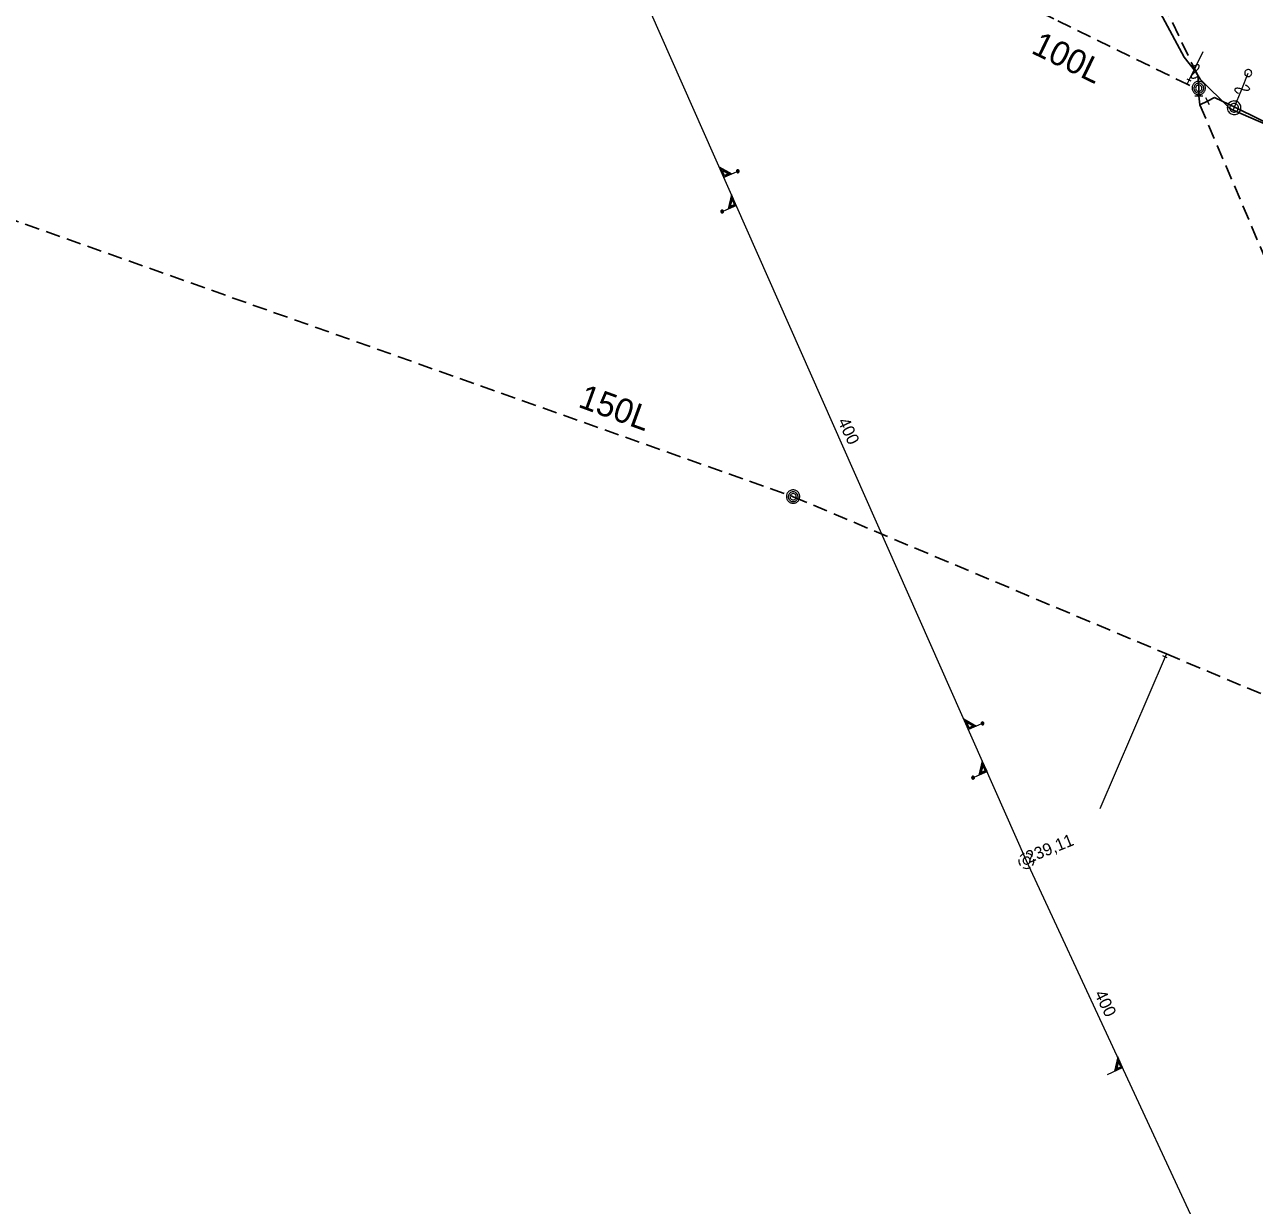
# Model space of a CAD drawing. Extents: x -735085 to -733500, y -1044153 to -1043402.
# Drawn here: x -734892.7 to -734812.1, y -1043597 to -1043519.6 of the extents above; entities that cross this region are included whole.
import ezdxf

# ---------------------------------------------------------------- set-up
doc = ezdxf.new("R2010")
doc.units = 0
doc.header["$LTSCALE"] = 0.32
doc.linetypes.add('MEDIUM_DASHED', pattern=[4.5, 3, -1.5])
doc.layers.add('15', color=7, linetype='Continuous')
doc.layers.add('16', color=7, linetype='Continuous')
for name, color, linetype, lineweight in [('18', 7, 'Continuous', 13), ('20', 7, 'Continuous', 13), ('8', 7, 'Continuous', 13)]:
    doc.layers.add(name, color=color, linetype=linetype, lineweight=lineweight)

msp = doc.modelspace()

# ---------------------------------------------------------------- linework, layer by layer
at = {"layer": '18'}
for points in [[(-734845.879, -1043529.18), (-734846.88, -1043529.624), (-734847.192, -1043528.92), (-734846.352, -1043529.389)], [(-734846.48, -1043529.391), (-734846.86, -1043529.56), (-734847.089, -1043529.043), (-734846.479, -1043529.391)], [(-734846.576, -1043529.383), (-734846.842, -1043529.501), (-734846.993, -1043529.161), (-734846.575, -1043529.383)], [(-734847.077, -1043531.897), (-734846.076, -1043531.453), (-734846.389, -1043530.748), (-734846.605, -1043531.687)], [(-734846.517, -1043531.593), (-734846.136, -1043531.424), (-734846.366, -1043530.907), (-734846.518, -1043531.593)], [(-734846.46, -1043531.516), (-734846.193, -1043531.398), (-734846.343, -1043531.058), (-734846.459, -1043531.517)], [(-734829.833, -1043565.381), (-734830.834, -1043565.825), (-734831.146, -1043565.121), (-734830.306, -1043565.59)], [(-734830.434, -1043565.592), (-734830.814, -1043565.761), (-734831.043, -1043565.244), (-734830.433, -1043565.592)], [(-734830.53, -1043565.584), (-734830.796, -1043565.702), (-734830.947, -1043565.362), (-734830.529, -1043565.584)], [(-734830.625, -1043569.012), (-734829.624, -1043568.568), (-734829.937, -1043567.863), (-734830.153, -1043568.802)], [(-734830.065, -1043568.708), (-734829.684, -1043568.539), (-734829.914, -1043568.022), (-734830.066, -1043568.708)], [(-734830.008, -1043568.631), (-734829.741, -1043568.513), (-734829.891, -1043568.173), (-734830.007, -1043568.632)], [(-734827.528, -1043574.349), (-734827.534, -1043574.426), (-734827.529, -1043574.503), (-734827.512, -1043574.578), (-734827.483, -1043574.649), (-734827.443, -1043574.715), (-734827.427, -1043574.737)], [(-734827.183, -1043573.957), (-734827.254, -1043573.985), (-734827.321, -1043574.024), (-734827.381, -1043574.072), (-734827.432, -1043574.129), (-734827.456, -1043574.163)], [(-734826.642, -1043574.14), (-734826.692, -1043574.082), (-734826.75, -1043574.032), (-734826.815, -1043573.991), (-734826.886, -1043573.962), (-734826.935, -1043573.948)], [(-734826.647, -1043574.726), (-734826.606, -1043574.661), (-734826.575, -1043574.591), (-734826.556, -1043574.516), (-734826.548, -1043574.44), (-734826.553, -1043574.363), (-734826.559, -1043574.328)], [(-734827.27, -1043574.866), (-734827.2, -1043574.897), (-734827.125, -1043574.916), (-734827.049, -1043574.923), (-734826.972, -1043574.918), (-734826.897, -1043574.901), (-734826.825, -1043574.873), (-734826.765, -1043574.838)], [(-734821.725, -1043588.443), (-734820.731, -1043587.982), (-734821.056, -1043587.282), (-734821.255, -1043588.225)], [(-734821.17, -1043588.129), (-734820.792, -1043587.954), (-734821.03, -1043587.442), (-734821.171, -1043588.13)], [(-734821.113, -1043588.051), (-734820.849, -1043587.929), (-734821.005, -1043587.592), (-734821.113, -1043588.052)]]:
    msp.add_lwpolyline(points, dxfattribs=at)
for points in [[(-734846.003, -1043529.132), (-734846.031, -1043529.151), (-734846.05, -1043529.178), (-734846.059, -1043529.21), (-734846.055, -1043529.244), (-734846.041, -1043529.274), (-734846.016, -1043529.297), (-734845.985, -1043529.31), (-734845.952, -1043529.312), (-734845.92, -1043529.301), (-734845.894, -1043529.281), (-734845.876, -1043529.252), (-734845.87, -1043529.219), (-734845.876, -1043529.186), (-734845.893, -1043529.156), (-734845.918, -1043529.135), (-734845.95, -1043529.125), (-734845.984, -1043529.126)], [(-734845.993, -1043529.157), (-734846.016, -1043529.174), (-734846.031, -1043529.198), (-734846.032, -1043529.226), (-734846.024, -1043529.253), (-734846.005, -1043529.274), (-734845.978, -1043529.284), (-734845.95, -1043529.284), (-734845.925, -1043529.271), (-734845.907, -1043529.25), (-734845.899, -1043529.223), (-734845.903, -1043529.195), (-734845.918, -1043529.171), (-734845.942, -1043529.155), (-734845.969, -1043529.151)], [(-734847.03, -1043531.772), (-734847.058, -1043531.791), (-734847.077, -1043531.818), (-734847.086, -1043531.85), (-734847.082, -1043531.884), (-734847.068, -1043531.913), (-734847.043, -1043531.937), (-734847.012, -1043531.95), (-734846.979, -1043531.952), (-734846.947, -1043531.942), (-734846.92, -1043531.92), (-734846.903, -1043531.892), (-734846.897, -1043531.86), (-734846.903, -1043531.826), (-734846.919, -1043531.797), (-734846.945, -1043531.776), (-734846.977, -1043531.765), (-734847.011, -1043531.766)], [(-734847.017, -1043531.796), (-734847.04, -1043531.813), (-734847.054, -1043531.838), (-734847.058, -1043531.865), (-734847.048, -1043531.892), (-734847.029, -1043531.913), (-734847.003, -1043531.924), (-734846.975, -1043531.924), (-734846.949, -1043531.911), (-734846.931, -1043531.889), (-734846.923, -1043531.862), (-734846.927, -1043531.834), (-734846.942, -1043531.811), (-734846.966, -1043531.795), (-734846.994, -1043531.79)], [(-734829.957, -1043565.333), (-734829.985, -1043565.352), (-734830.004, -1043565.379), (-734830.013, -1043565.411), (-734830.009, -1043565.445), (-734829.995, -1043565.475), (-734829.97, -1043565.498), (-734829.939, -1043565.511), (-734829.906, -1043565.513), (-734829.874, -1043565.502), (-734829.848, -1043565.482), (-734829.83, -1043565.453), (-734829.824, -1043565.42), (-734829.83, -1043565.387), (-734829.847, -1043565.357), (-734829.872, -1043565.336), (-734829.904, -1043565.326), (-734829.938, -1043565.327)], [(-734829.947, -1043565.358), (-734829.97, -1043565.375), (-734829.985, -1043565.399), (-734829.986, -1043565.427), (-734829.978, -1043565.454), (-734829.959, -1043565.475), (-734829.932, -1043565.485), (-734829.904, -1043565.485), (-734829.879, -1043565.472), (-734829.861, -1043565.451), (-734829.853, -1043565.424), (-734829.857, -1043565.396), (-734829.872, -1043565.372), (-734829.896, -1043565.356), (-734829.923, -1043565.352)], [(-734830.578, -1043568.887), (-734830.606, -1043568.906), (-734830.625, -1043568.933), (-734830.634, -1043568.965), (-734830.63, -1043568.999), (-734830.616, -1043569.028), (-734830.591, -1043569.052), (-734830.56, -1043569.065), (-734830.527, -1043569.067), (-734830.495, -1043569.057), (-734830.468, -1043569.035), (-734830.451, -1043569.007), (-734830.445, -1043568.975), (-734830.451, -1043568.941), (-734830.467, -1043568.912), (-734830.493, -1043568.891), (-734830.525, -1043568.88), (-734830.559, -1043568.881)], [(-734830.565, -1043568.911), (-734830.588, -1043568.928), (-734830.602, -1043568.953), (-734830.606, -1043568.98), (-734830.596, -1043569.007), (-734830.577, -1043569.028), (-734830.551, -1043569.039), (-734830.523, -1043569.039), (-734830.497, -1043569.026), (-734830.479, -1043569.004), (-734830.471, -1043568.977), (-734830.475, -1043568.949), (-734830.49, -1043568.926), (-734830.514, -1043568.91), (-734830.542, -1043568.905)], [(-734826.799, -1043574.409), (-734826.805, -1043574.357), (-734826.823, -1043574.307), (-734826.851, -1043574.263), (-734826.889, -1043574.226), (-734826.934, -1043574.199), (-734826.984, -1043574.183), (-734827.036, -1043574.178), (-734827.088, -1043574.185), (-734827.137, -1043574.204), (-734827.181, -1043574.234), (-734827.216, -1043574.273), (-734827.242, -1043574.318), (-734827.257, -1043574.369), (-734827.26, -1043574.421), (-734827.252, -1043574.473), (-734827.231, -1043574.521), (-734827.201, -1043574.564), (-734827.161, -1043574.599), (-734827.115, -1043574.623), (-734827.064, -1043574.637), (-734827.012, -1043574.639), (-734826.96, -1043574.629), (-734826.912, -1043574.607), (-734826.87, -1043574.575), (-734826.837, -1043574.535), (-734826.813, -1043574.488), (-734826.801, -1043574.437)]]:
    msp.add_lwpolyline(points, close=True, dxfattribs=at)
at = {"layer": '20'}
for p, q in [((-734827.03, -1043574.42), (-734851.719, -1043518.72)), ((-734827.03, -1043574.42), (-734851.719, -1043518.72)), ((-734813.87, -1043602.77), (-734827.03, -1043574.42)), ((-734813.87, -1043602.77), (-734827.03, -1043574.42))]:
    msp.add_line(p, q, dxfattribs=at)
at = {"layer": '8'}
for p, q in [((-734816.366, -1043523.248), (-734815.441, -1043521.359)), ((-734816.235, -1043523.312), (-734816.508, -1043523.178)), ((-734816.498, -1043523.517), (-734816.366, -1043523.248)), ((-734815.998, -1043524.264), (-734815.481, -1043524.275)), ((-734815.286, -1043524.388), (-734815.051, -1043524.849)), ((-734817.864, -1043560.858), (-734817.949, -1043561.059)), ((-734817.949, -1043561.059), (-734822.219, -1043571.021)), ((-734817.815, -1043561.115), (-734818.094, -1043560.995))]:
    msp.add_line(p, q, dxfattribs=at)
at = {"layer": '8', "lineweight": 25}
msp.add_line((-734816.109, -1043522.33), (-734815.92, -1043522.69), dxfattribs=at)
at = {"layer": '8', "linetype": 'MEDIUM_DASHED', "lineweight": 25}
msp.add_line((-734815.66, -1043524.87), (-734805.897, -1043547.809), dxfattribs=at)
for points in [[(-734882.879, -1043402.28), (-734843, -1043481.39), (-734832.66, -1043494.6), (-734826.809, -1043502.83), (-734821.69, -1043510.97), (-734819.3, -1043515.56), (-734816.109, -1043522.33)], [(-734831.274, -1043516.278), (-734824.991, -1043519.356), (-734816.498, -1043523.517), (-734816.333, -1043523.597)], [(-734928.23, -1043519.739), (-734905.133, -1043527.879), (-734903.548, -1043528.837), (-734842.335, -1043550.559)], [(-734816.162, -1043522.174), (-734815.809, -1043522.93), (-734815.73, -1043523.77), (-734815.739, -1043524.27), (-734815.66, -1043524.87), (-734815.17, -1043524.62), (-734814.717, -1043524.389)], [(-734842.335, -1043550.559), (-734817.864, -1043560.858), (-734785.16, -1043574.621)]]:
    msp.add_lwpolyline(points, dxfattribs=at)
at = {"layer": '8', "lineweight": 25}
for points in [[(-734839.59, -1043484.83), (-734833.43, -1043493.7), (-734828.809, -1043500.35), (-734825.489, -1043505.26), (-734823.69, -1043508.71), (-734816.69, -1043521.74), (-734815.949, -1043522.67)], [(-734815.949, -1043522.67), (-734815.649, -1043523.18), (-734813.73, -1043525.08), (-734813.489, -1043525.21), (-734810.149, -1043526.65), (-734804.64, -1043529.36)], [(-734814.717, -1043524.389), (-734813.287, -1043525.06), (-734798.77, -1043532.2), (-734792.71, -1043535.18)]]:
    msp.add_lwpolyline(points, dxfattribs=at)
at = {"layer": '8'}
for points in [[(-734815.947, -1043522.668), (-734815.893, -1043522.621), (-734815.844, -1043522.572), (-734815.801, -1043522.522), (-734815.764, -1043522.472), (-734815.737, -1043522.424), (-734815.717, -1043522.379), (-734815.708, -1043522.339), (-734815.707, -1043522.305), (-734815.718, -1043522.278), (-734815.737, -1043522.257), (-734815.765, -1043522.245), (-734815.8, -1043522.241), (-734815.843, -1043522.246), (-734815.893, -1043522.258), (-734815.946, -1043522.279), (-734816.002, -1043522.307), (-734816.06, -1043522.342), (-734816.085, -1043522.359)], [(-734815.803, -1043523.012), (-734815.865, -1043523.049), (-734815.927, -1043523.08), (-734815.985, -1043523.104), (-734816.041, -1043523.12), (-734816.09, -1043523.128), (-734816.133, -1043523.129), (-734816.168, -1043523.122), (-734816.195, -1043523.106), (-734816.212, -1043523.083), (-734816.22, -1043523.052), (-734816.218, -1043523.016), (-734816.206, -1043522.974), (-734816.185, -1043522.928), (-734816.154, -1043522.879), (-734816.115, -1043522.829), (-734816.069, -1043522.777), (-734816.017, -1043522.728), (-734815.961, -1043522.679), (-734815.944, -1043522.667)], [(-734813.489, -1043525.21), (-734813.41, -1043525.06), (-734812.92, -1043523.84), (-734812.488, -1043522.784)], [(-734815.299, -1043523.758), (-734815.302, -1043523.713), (-734815.309, -1043523.668), (-734815.321, -1043523.623), (-734815.337, -1043523.581), (-734815.358, -1043523.54), (-734815.383, -1043523.501), (-734815.412, -1043523.466), (-734815.444, -1043523.433), (-734815.48, -1043523.405), (-734815.517, -1043523.38), (-734815.559, -1043523.359), (-734815.602, -1043523.342), (-734815.646, -1043523.33), (-734815.691, -1043523.323), (-734815.737, -1043523.321), (-734815.782, -1043523.323), (-734815.828, -1043523.33), (-734815.872, -1043523.342), (-734815.915, -1043523.359), (-734815.956, -1043523.38), (-734815.994, -1043523.405), (-734816.03, -1043523.433), (-734816.062, -1043523.466), (-734816.091, -1043523.501), (-734816.116, -1043523.54), (-734816.137, -1043523.581), (-734816.152, -1043523.623), (-734816.165, -1043523.668), (-734816.172, -1043523.713), (-734816.174, -1043523.759), (-734816.172, -1043523.804), (-734816.165, -1043523.849), (-734816.152, -1043523.894), (-734816.137, -1043523.936), (-734816.116, -1043523.977), (-734816.091, -1043524.016), (-734816.062, -1043524.051), (-734816.03, -1043524.084), (-734815.994, -1043524.112), (-734815.956, -1043524.137), (-734815.915, -1043524.158), (-734815.872, -1043524.175), (-734815.828, -1043524.186), (-734815.782, -1043524.194), (-734815.737, -1043524.196), (-734815.691, -1043524.194), (-734815.646, -1043524.186), (-734815.602, -1043524.175), (-734815.559, -1043524.158), (-734815.517, -1043524.137), (-734815.48, -1043524.112), (-734815.444, -1043524.084), (-734815.412, -1043524.051), (-734815.383, -1043524.016), (-734815.358, -1043523.977), (-734815.337, -1043523.936), (-734815.321, -1043523.894), (-734815.309, -1043523.849), (-734815.302, -1043523.804), (-734815.299, -1043523.759)], [(-734812.922, -1043523.839), (-734812.989, -1043523.815), (-734813.056, -1043523.797), (-734813.121, -1043523.784), (-734813.183, -1043523.777), (-734813.237, -1043523.776), (-734813.286, -1043523.782), (-734813.325, -1043523.794), (-734813.355, -1043523.81), (-734813.374, -1043523.833), (-734813.383, -1043523.859), (-734813.38, -1043523.89), (-734813.365, -1043523.922), (-734813.34, -1043523.957), (-734813.304, -1043523.994), (-734813.261, -1043524.03), (-734813.208, -1043524.065), (-734813.149, -1043524.099), (-734813.122, -1043524.112)], [(-734812.694, -1043523.544), (-734812.63, -1043523.58), (-734812.573, -1043523.618), (-734812.523, -1043523.657), (-734812.482, -1043523.697), (-734812.451, -1043523.736), (-734812.429, -1043523.773), (-734812.418, -1043523.807), (-734812.418, -1043523.838), (-734812.43, -1043523.865), (-734812.453, -1043523.887), (-734812.485, -1043523.903), (-734812.527, -1043523.913), (-734812.578, -1043523.917), (-734812.636, -1043523.915), (-734812.699, -1043523.906), (-734812.766, -1043523.891), (-734812.835, -1043523.87), (-734812.905, -1043523.845), (-734812.924, -1043523.837)], [(-734841.904, -1043550.547), (-734841.907, -1043550.502), (-734841.914, -1043550.457), (-734841.926, -1043550.412), (-734841.941, -1043550.37), (-734841.963, -1043550.329), (-734841.988, -1043550.29), (-734842.017, -1043550.255), (-734842.049, -1043550.222), (-734842.085, -1043550.194), (-734842.122, -1043550.169), (-734842.164, -1043550.148), (-734842.206, -1043550.131), (-734842.25, -1043550.119), (-734842.296, -1043550.112), (-734842.342, -1043550.11), (-734842.387, -1043550.112), (-734842.433, -1043550.119), (-734842.477, -1043550.131), (-734842.52, -1043550.148), (-734842.561, -1043550.169), (-734842.598, -1043550.194), (-734842.635, -1043550.222), (-734842.667, -1043550.255), (-734842.696, -1043550.29), (-734842.721, -1043550.329), (-734842.742, -1043550.37), (-734842.757, -1043550.412), (-734842.77, -1043550.457), (-734842.777, -1043550.502), (-734842.779, -1043550.548), (-734842.777, -1043550.593), (-734842.77, -1043550.638), (-734842.757, -1043550.683), (-734842.742, -1043550.725), (-734842.721, -1043550.766), (-734842.696, -1043550.805), (-734842.667, -1043550.84), (-734842.635, -1043550.873), (-734842.598, -1043550.901), (-734842.561, -1043550.926), (-734842.52, -1043550.947), (-734842.477, -1043550.964), (-734842.433, -1043550.975), (-734842.387, -1043550.983), (-734842.342, -1043550.985), (-734842.296, -1043550.983), (-734842.25, -1043550.975), (-734842.206, -1043550.964), (-734842.164, -1043550.947), (-734842.122, -1043550.926), (-734842.085, -1043550.901), (-734842.049, -1043550.873), (-734842.017, -1043550.84), (-734841.988, -1043550.805), (-734841.963, -1043550.766), (-734841.941, -1043550.725), (-734841.926, -1043550.683), (-734841.914, -1043550.638), (-734841.907, -1043550.593), (-734841.904, -1043550.548)]]:
    msp.add_lwpolyline(points, dxfattribs=at)
for points in [[(-734812.417, -1043522.563), (-734812.467, -1043522.551), (-734812.521, -1043522.55), (-734812.572, -1043522.561), (-734812.62, -1043522.584), (-734812.661, -1043522.617), (-734812.693, -1043522.658), (-734812.716, -1043522.705), (-734812.727, -1043522.756), (-734812.727, -1043522.808), (-734812.714, -1043522.86), (-734812.69, -1043522.907), (-734812.657, -1043522.947), (-734812.614, -1043522.979), (-734812.566, -1043523), (-734812.515, -1043523.01), (-734812.463, -1043523.007), (-734812.412, -1043522.994), (-734812.365, -1043522.969), (-734812.327, -1043522.934), (-734812.296, -1043522.891), (-734812.276, -1043522.843), (-734812.267, -1043522.791), (-734812.271, -1043522.738), (-734812.286, -1043522.688), (-734812.312, -1043522.643), (-734812.348, -1043522.604), (-734812.391, -1043522.575)], [(-734815.413, -1043523.766), (-734815.419, -1043523.705), (-734815.437, -1043523.645), (-734815.466, -1043523.59), (-734815.505, -1043523.542), (-734815.552, -1043523.502), (-734815.606, -1043523.472), (-734815.665, -1043523.452), (-734815.727, -1043523.445), (-734815.789, -1043523.449), (-734815.848, -1043523.465), (-734815.904, -1043523.493), (-734815.954, -1043523.53), (-734815.995, -1043523.577), (-734816.027, -1043523.63), (-734816.047, -1043523.689), (-734816.057, -1043523.75), (-734816.054, -1043523.812), (-734816.039, -1043523.872), (-734816.013, -1043523.929), (-734815.977, -1043523.979), (-734815.931, -1043524.022), (-734815.879, -1043524.054), (-734815.821, -1043524.077), (-734815.76, -1043524.087), (-734815.698, -1043524.086), (-734815.637, -1043524.073), (-734815.58, -1043524.048), (-734815.529, -1043524.013), (-734815.485, -1043523.969), (-734815.451, -1043523.917), (-734815.427, -1043523.86), (-734815.415, -1043523.799)], [(-734815.527, -1043523.766), (-734815.532, -1043523.717), (-734815.549, -1043523.67), (-734815.578, -1043523.629), (-734815.616, -1043523.596), (-734815.66, -1043523.572), (-734815.708, -1043523.56), (-734815.758, -1043523.559), (-734815.806, -1043523.571), (-734815.851, -1043523.593), (-734815.889, -1043523.626), (-734815.918, -1043523.666), (-734815.937, -1043523.713), (-734815.944, -1043523.762), (-734815.939, -1043523.812), (-734815.922, -1043523.859), (-734815.895, -1043523.901), (-734815.858, -1043523.935), (-734815.815, -1043523.959), (-734815.767, -1043523.973), (-734815.717, -1043523.974), (-734815.668, -1043523.964), (-734815.623, -1043523.942), (-734815.584, -1043523.91), (-734815.554, -1043523.871), (-734815.535, -1043523.825), (-734815.527, -1043523.775)], [(-734813.224, -1043524.652), (-734813.293, -1043524.626), (-734813.365, -1043524.611), (-734813.437, -1043524.608), (-734813.51, -1043524.618), (-734813.581, -1043524.638), (-734813.646, -1043524.67), (-734813.705, -1043524.712), (-734813.758, -1043524.763), (-734813.801, -1043524.823), (-734813.834, -1043524.889), (-734813.855, -1043524.958), (-734813.865, -1043525.031), (-734813.863, -1043525.103), (-734813.849, -1043525.176), (-734813.824, -1043525.245), (-734813.788, -1043525.308), (-734813.741, -1043525.365), (-734813.687, -1043525.413), (-734813.624, -1043525.452), (-734813.557, -1043525.48), (-734813.486, -1043525.497), (-734813.413, -1043525.502), (-734813.34, -1043525.495), (-734813.269, -1043525.476), (-734813.203, -1043525.446), (-734813.142, -1043525.405), (-734813.088, -1043525.356), (-734813.043, -1043525.298), (-734813.009, -1043525.233), (-734812.985, -1043525.164), (-734812.973, -1043525.091), (-734812.974, -1043525.018), (-734812.985, -1043524.946), (-734813.009, -1043524.877), (-734813.044, -1043524.812), (-734813.088, -1043524.754), (-734813.142, -1043524.705), (-734813.202, -1043524.664)], [(-734813.294, -1043524.797), (-734813.349, -1043524.778), (-734813.408, -1043524.769), (-734813.466, -1043524.772), (-734813.522, -1043524.788), (-734813.575, -1043524.814), (-734813.62, -1043524.851), (-734813.658, -1043524.896), (-734813.685, -1043524.948), (-734813.701, -1043525.004), (-734813.705, -1043525.063), (-734813.698, -1043525.121), (-734813.679, -1043525.176), (-734813.648, -1043525.226), (-734813.608, -1043525.27), (-734813.561, -1043525.304), (-734813.507, -1043525.328), (-734813.45, -1043525.34), (-734813.391, -1043525.34), (-734813.334, -1043525.328), (-734813.28, -1043525.305), (-734813.233, -1043525.272), (-734813.192, -1043525.229), (-734813.161, -1043525.179), (-734813.142, -1043525.125), (-734813.133, -1043525.067), (-734813.136, -1043525.008), (-734813.152, -1043524.952), (-734813.179, -1043524.9), (-734813.215, -1043524.855), (-734813.261, -1043524.817)], [(-734842.017, -1043550.555), (-734842.024, -1043550.494), (-734842.042, -1043550.434), (-734842.071, -1043550.379), (-734842.11, -1043550.331), (-734842.157, -1043550.291), (-734842.211, -1043550.261), (-734842.27, -1043550.241), (-734842.331, -1043550.234), (-734842.394, -1043550.238), (-734842.453, -1043550.254), (-734842.509, -1043550.282), (-734842.559, -1043550.319), (-734842.6, -1043550.366), (-734842.632, -1043550.419), (-734842.652, -1043550.478), (-734842.662, -1043550.539), (-734842.659, -1043550.601), (-734842.644, -1043550.661), (-734842.618, -1043550.718), (-734842.581, -1043550.768), (-734842.536, -1043550.811), (-734842.483, -1043550.843), (-734842.426, -1043550.866), (-734842.365, -1043550.876), (-734842.303, -1043550.875), (-734842.242, -1043550.862), (-734842.184, -1043550.837), (-734842.134, -1043550.802), (-734842.09, -1043550.758), (-734842.056, -1043550.706), (-734842.032, -1043550.649), (-734842.02, -1043550.588)], [(-734842.132, -1043550.555), (-734842.137, -1043550.506), (-734842.154, -1043550.459), (-734842.183, -1043550.418), (-734842.221, -1043550.385), (-734842.265, -1043550.361), (-734842.313, -1043550.349), (-734842.363, -1043550.348), (-734842.411, -1043550.36), (-734842.456, -1043550.382), (-734842.494, -1043550.415), (-734842.522, -1043550.455), (-734842.542, -1043550.502), (-734842.549, -1043550.551), (-734842.544, -1043550.601), (-734842.527, -1043550.648), (-734842.5, -1043550.69), (-734842.463, -1043550.724), (-734842.419, -1043550.748), (-734842.372, -1043550.762), (-734842.321, -1043550.763), (-734842.272, -1043550.753), (-734842.228, -1043550.731), (-734842.189, -1043550.699), (-734842.159, -1043550.66), (-734842.14, -1043550.614), (-734842.132, -1043550.564)]]:
    msp.add_lwpolyline(points, close=True, dxfattribs=at)

# ---------------------------------------------------------------- texts
at = {"layer": '15'}
for s, rotation, p in [('100L', 334, (-734826.801, -1043521.434)), ('150L', 340, (-734856.509, -1043544.648))]:
    msp.add_text(s, height=1.6, rotation=rotation, dxfattribs=at).set_placement(p)
at = {"layer": '16'}
for s, rotation, p in [('400 ', 295, (-734839.434, -1043545.607)), ('239,11', 22, (-734826.893, -1043574.598)), ('400 ', 296, (-734822.604, -1043583.144))]:
    msp.add_text(s, height=0.8, rotation=rotation, dxfattribs=at).set_placement(p)

doc.saveas('drawing.dxf')
